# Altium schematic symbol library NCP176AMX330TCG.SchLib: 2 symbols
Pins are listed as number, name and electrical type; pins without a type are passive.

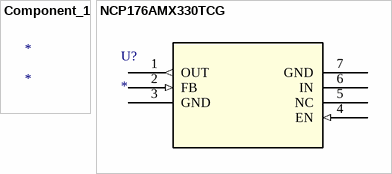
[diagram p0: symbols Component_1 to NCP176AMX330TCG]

## Component_1
designator *

## NCP176AMX330TCG
designator U?
No Description Available; Mfr_Name: onsemi
footprint XDFN6_711AT_ONS
pins: 1 OUT (out), 2 FB (in), 3 GND (power), 4 EN (in), 5 NC, 6 IN (power), 7 GND (power)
